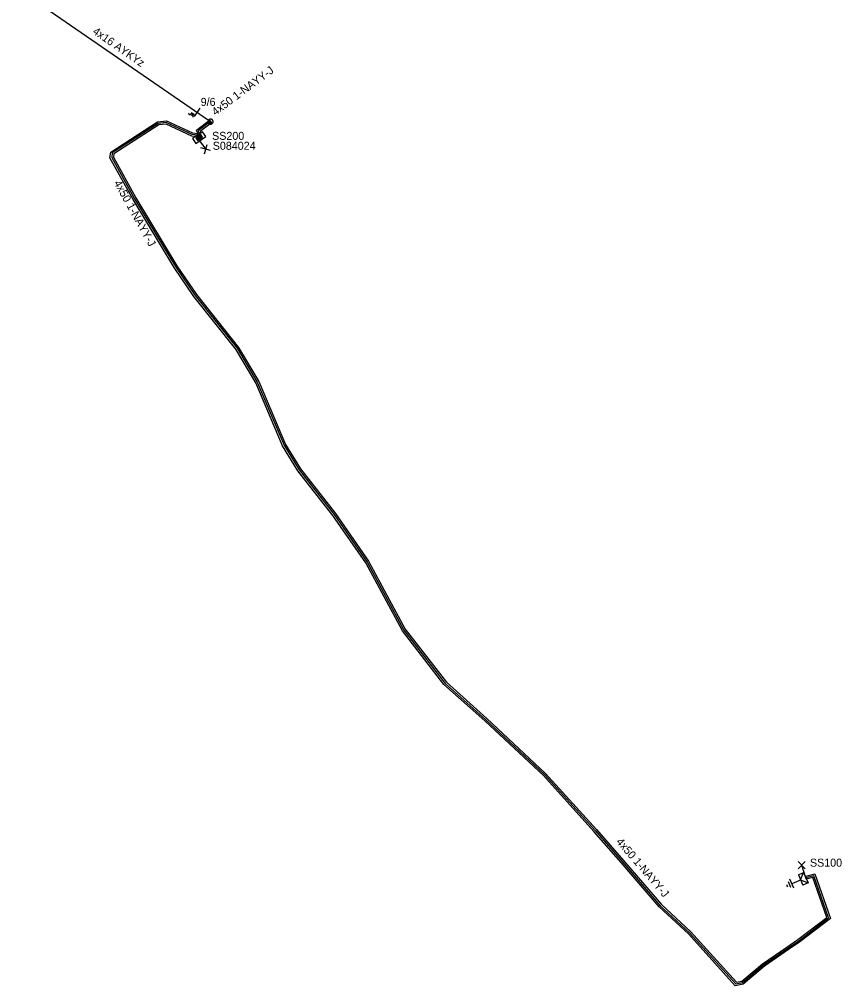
# Model space of a CAD drawing. Extents: x -788458 to -786145, y -1154772 to -1152372.
# Drawn here: x -786247.3 to -786144.5, y -1153657.7 to -1153537 of the extents above; entities that cross this region are included whole.
import ezdxf

# ---------------------------------------------------------------- set-up
doc = ezdxf.new("R2010")
doc.units = 0
for name, color, linetype in [('Vrstva 1', 7, 'Continuous'), ('Vrstva 12', 7, 'Continuous'), ('Vrstva 13', 7, 'Continuous'), ('Vrstva 14', 7, 'Continuous'), ('Vrstva 15', 7, 'Continuous'), ('Vrstva 18', 7, 'Continuous'), ('Vrstva 2', 7, 'Continuous'), ('Vrstva 20', 7, 'Continuous'), ('Vrstva 28', 7, 'Continuous'), ('Vrstva 29', 7, 'Continuous'), ('Vrstva 30', 7, 'Continuous'), ('Vrstva 31', 7, 'Continuous'), ('Vrstva 33', 7, 'Continuous'), ('Vrstva 34', 7, 'Continuous'), ('Vrstva 5', 7, 'Continuous'), ('Vrstva 52', 7, 'Continuous'), ('Vrstva 53', 7, 'Continuous'), ('Vrstva 59', 7, 'Continuous'), ('Vrstva 6', 7, 'Continuous'), ('Vrstva 8', 7, 'Continuous'), ('Vrstva 9', 7, 'Continuous')]:
    doc.layers.add(name, color=color, linetype=linetype)

# ---------------------------------------------------------------- blocks, each defined once
blk = doc.blocks.new('NN440')
at = {"layer": 'Vrstva 2'}
for points in [[(0.63, 0), (0.63, 0.06), (0.62, 0.13), (0.6, 0.19), (0.58, 0.25), (0.55, 0.31), (0.51, 0.37), (0.47, 0.42), (0.42, 0.46), (0.37, 0.51), (0.32, 0.54), (0.26, 0.57), (0.2, 0.59), (0.13, 0.61), (0.07, 0.62), (0, 0.63), (-0.06, 0.62), (-0.13, 0.61), (-0.19, 0.59), (-0.26, 0.57), (-0.31, 0.54), (-0.37, 0.51), (-0.42, 0.46), (-0.47, 0.42), (-0.51, 0.37), (-0.54, 0.31), (-0.57, 0.25), (-0.6, 0.19), (-0.62, 0.13), (-0.63, 0.06), (-0.63, 0), (-0.63, -0.07), (-0.62, -0.14), (-0.6, -0.2), (-0.57, -0.26), (-0.54, -0.32), (-0.51, -0.37), (-0.47, -0.43), (-0.42, -0.47), (-0.37, -0.51), (-0.31, -0.55), (-0.26, -0.58), (-0.19, -0.6), (-0.13, -0.62), (-0.06, -0.63), (0, -0.63), (0.07, -0.63), (0.13, -0.62), (0.2, -0.6), (0.26, -0.58), (0.32, -0.55), (0.37, -0.51), (0.42, -0.47), (0.47, -0.43), (0.51, -0.37), (0.55, -0.32), (0.58, -0.26), (0.6, -0.2), (0.62, -0.14), (0.63, -0.07), (0.63, 0)], [(-0.63, 0), (0.63, 0)], [(-0.6, -0.18), (0.57, -0.18)], [(-0.51, -0.32), (0.5, -0.32)], [(-0.37, -0.47), (0.35, -0.47)]]:
    blk.add_lwpolyline(points, dxfattribs=at)
blk = doc.blocks.new('NN840')
at = {"layer": 'Vrstva 15'}
for points in [[(0, 0.62), (0, -0.63)], [(-0.75, -0.71), (-0.75, -0.66)], [(-0.73, -0.76), (-0.75, -0.71)], [(-0.66, -0.8), (-0.73, -0.76)], [(-0.63, -0.8), (-0.66, -0.8)], [(-0.56, -0.76), (-0.63, -0.8)], [(-0.54, -0.71), (-0.56, -0.76)], [(-0.54, -0.38), (-0.54, -0.71)], [(-0.33, -0.38), (-0.33, -0.8)], [(-0.33, -0.64), (-0.13, -0.38)], [(-0.26, -0.56), (-0.09, -0.8)]]:
    blk.add_lwpolyline(points, dxfattribs=at)
blk = doc.blocks.new('NN800')
at = {"layer": 'Vrstva 1'}
for points in [[(-0.44, 0.44), (0.44, -0.44)], [(-0.44, -0.44), (0.44, 0.44)]]:
    blk.add_lwpolyline(points, dxfattribs=at)
blk = doc.blocks.new('NN620')
at = {"layer": 'Vrstva 8'}
for points in [[(0.75, 0), (-0.75, 0)], [(-0.75, 0), (-0.75, -0.75)], [(0.75, -0.75), (0.75, 0)], [(-0.75, -0.75), (0.75, -0.75)], [(0.37, -0.18), (-0.38, -0.18)], [(-0.38, -0.18), (-0.38, -0.56)], [(-0.38, -0.56), (0.37, -0.56)], [(0.32, -0.23), (-0.33, -0.23)], [(-0.33, -0.23), (-0.33, -0.51)], [(-0.33, -0.51), (0.32, -0.51)], [(0.27, -0.27), (-0.28, -0.27)], [(-0.28, -0.27), (-0.28, -0.46)], [(-0.28, -0.46), (0.27, -0.46)], [(0.23, -0.32), (-0.23, -0.32)], [(-0.23, -0.32), (-0.23, -0.42)], [(-0.23, -0.42), (0.23, -0.42)], [(-0.19, -0.37), (0.19, -0.37)], [(0.23, -0.42), (0.23, -0.32)], [(0.27, -0.46), (0.27, -0.27)], [(0.32, -0.51), (0.32, -0.23)], [(0.37, -0.56), (0.37, -0.18)]]:
    blk.add_lwpolyline(points, dxfattribs=at)
blk = doc.blocks.new('NN630')
at = {"layer": 'Vrstva 9'}
for points in [[(0, -0.7), (-0.7, 0)], [(-0.7, -0.7), (-0.7, 0), (0.7, 0), (0.7, -0.7)], [(-0.7, -0.7), (0.7, -0.7)], [(0, -0.7), (0.7, 0)]]:
    blk.add_lwpolyline(points, dxfattribs=at)
blk = doc.blocks.new('NN810')
at = {"layer": 'Vrstva 14'}
for points in [[(0, -0.64), (0, -1.89)], [(0.63, -1.89), (-0.62, -1.89)], [(0.39, -2.2), (-0.4, -2.2)], [(0, -2.52), (-0.12, -2.52)], [(0.14, -2.52), (0, -2.52)]]:
    blk.add_lwpolyline(points, dxfattribs=at)

msp = doc.modelspace()

# ---------------------------------------------------------------- linework, layer by layer
at = {"layer": 'Vrstva 20'}
for points in [[(-786223.24, -1153549.95), (-786224.66, -1153551.01), (-786224.56, -1153551.23), (-786224.93, -1153551.38), (-786225.14, -1153550.87), (-786223.48, -1153549.63)], [(-786225.02, -1153551.67), (-786225.71, -1153551.6), (-786228.93, -1153550.1), (-786229.84, -1153550.2), (-786235.45, -1153553.83), (-786235.51, -1153554.24), (-786232.69, -1153559.32), (-786227.58, -1153567.79), (-786225.13, -1153571.39), (-786219.87, -1153577.99), (-786217.34, -1153582.24), (-786214, -1153590.11), (-786212.14, -1153593.17), (-786207.75, -1153598.75), (-786203.61, -1153604.7), (-786199.06, -1153613.18), (-786193.9, -1153619.81), (-786188.84, -1153624.34), (-786181.5, -1153631.19), (-786175.16, -1153638.19), (-786171.77, -1153642.07), (-786167.03, -1153647.58), (-786163.38, -1153650.94), (-786157.66, -1153657.26), (-786156.99, -1153657.13), (-786154.38, -1153654.95), (-786151.37, -1153652.88), (-786149.97, -1153651.92), (-786146.38, -1153649.17), (-786148.13, -1153644.2), (-786148.94, -1153644.4), (-786149.04, -1153644.02), (-786147.87, -1153643.72), (-786145.9, -1153649.31), (-786149.73, -1153652.24), (-786151.15, -1153653.2), (-786154.14, -1153655.27), (-786156.81, -1153657.51), (-786157.8, -1153657.7), (-786163.66, -1153651.22), (-786167.31, -1153647.86), (-786172.07, -1153642.33), (-786175.46, -1153638.45), (-786181.78, -1153631.47), (-786189.1, -1153624.64), (-786194.2, -1153620.09), (-786199.4, -1153613.4), (-786203.95, -1153604.9), (-786208.07, -1153598.99), (-786212.46, -1153593.39), (-786214.36, -1153590.29), (-786217.7, -1153582.42), (-786220.19, -1153578.21), (-786225.45, -1153571.63), (-786227.92, -1153568.01), (-786233.03, -1153559.52), (-786235.93, -1153554.32), (-786235.83, -1153553.59), (-786229.98, -1153549.82), (-786228.87, -1153549.68), (-786225.61, -1153551.2), (-786224.98, -1153551.27)]]:
    msp.add_lwpolyline(points, close=True, dxfattribs=at)
at = {"layer": 'Vrstva 5'}
for points in [[(-786225, -1153551.47), (-786225.66, -1153551.4), (-786228.9, -1153549.89), (-786229.91, -1153550.01), (-786235.64, -1153553.71), (-786235.72, -1153554.28), (-786232.86, -1153559.42), (-786227.75, -1153567.9), (-786225.29, -1153571.51), (-786220.03, -1153578.1), (-786217.52, -1153582.33), (-786214.18, -1153590.2), (-786212.3, -1153593.28), (-786207.91, -1153598.87), (-786203.78, -1153604.8), (-786199.23, -1153613.29), (-786194.05, -1153619.95), (-786188.97, -1153624.49), (-786181.64, -1153631.33), (-786175.31, -1153638.32), (-786171.92, -1153642.2), (-786167.17, -1153647.72), (-786163.52, -1153651.08), (-786157.73, -1153657.48), (-786156.9, -1153657.32), (-786154.26, -1153655.11), (-786151.26, -1153653.04), (-786149.85, -1153652.08), (-786146.14, -1153649.24), (-786148, -1153643.96), (-786148.99, -1153644.21)], [(-786223.36, -1153549.79), (-786224.9, -1153550.94), (-786224.75, -1153551.3)]]:
    msp.add_lwpolyline(points, dxfattribs=at)
at = {"layer": 'Vrstva 52'}
msp.add_lwpolyline([(-786247.26, -1153533.29), (-786223.36, -1153549.79)], dxfattribs=at)
at = {"layer": 'Vrstva 59'}
for points in [[(-786224.78, -1153552.16), (-786223.96, -1153553.23)], [(-786148.99, -1153644.21), (-786149.49, -1153642.65)]]:
    msp.add_lwpolyline(points, dxfattribs=at)

# ---------------------------------------------------------------- block references
at = {"layer": 'Vrstva 13', "xscale": 0.5000000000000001, "yscale": 0.5, "rotation": -34.89440556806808}
msp.add_blockref('NN440', (-786223.36, -1153549.79), dxfattribs=at)
at = {"layer": 'Vrstva 15', "rotation": -66.50143428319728}
msp.add_blockref('NN810', (-786148.99, -1153644.21), dxfattribs=at)
at = {"layer": 'Vrstva 18', "rotation": -34.620310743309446}
msp.add_blockref('NN840', (-786225.04, -1153548.63), dxfattribs=at)
at = {"layer": 'Vrstva 28', "rotation": 34.186122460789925}
msp.add_blockref('NN620', (-786225, -1153551.47), dxfattribs=at)
at = {"layer": 'Vrstva 31', "rotation": -66.50143434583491}
msp.add_blockref('NN630', (-786148.99, -1153644.21), dxfattribs=at)
at = {"layer": 'Vrstva 34', "rotation": 119.3012305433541}
msp.add_blockref('NN800', (-786223.96, -1153553.23), dxfattribs=at)
at = {"layer": 'Vrstva 34'}
msp.add_blockref('NN800', (-786149.49, -1153642.65), dxfattribs=at)

# ---------------------------------------------------------------- texts
at = {"layer": 'Vrstva 12'}
msp.add_text('9/6', height=1, dxfattribs=at).set_placement((-786224.6, -1153547.83))
at = {"layer": 'Vrstva 29'}
msp.add_text('S084024', height=1, dxfattribs=at).set_placement((-786223.09, -1153553.31))
at = {"layer": 'Vrstva 30'}
msp.add_text('SS200', height=1, dxfattribs=at).set_placement((-786223.17, -1153552.07))
at = {"layer": 'Vrstva 33'}
msp.add_text('SS100', height=1, dxfattribs=at).set_placement((-786148.47, -1153642.84))
at = {"layer": 'Vrstva 53'}
msp.add_text('4x16 AYKYz', height=1, rotation=325.105, dxfattribs=at).set_placement((-786238.19, -1153538.73))
at = {"layer": 'Vrstva 6'}
for rotation, p in [(36.751, (-786222.75, -1153549.1)), (299.092, (-786235.49, -1153557.44)), (310.712, (-786172.75, -1153639.77))]:
    msp.add_text('4x50 1-NAYY-J', height=1, rotation=rotation, dxfattribs=at).set_placement(p)

doc.saveas('drawing.dxf')
